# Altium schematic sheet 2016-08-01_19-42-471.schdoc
size 295 x 121 mm; SheetNumber: 1; SheetTotal: 1
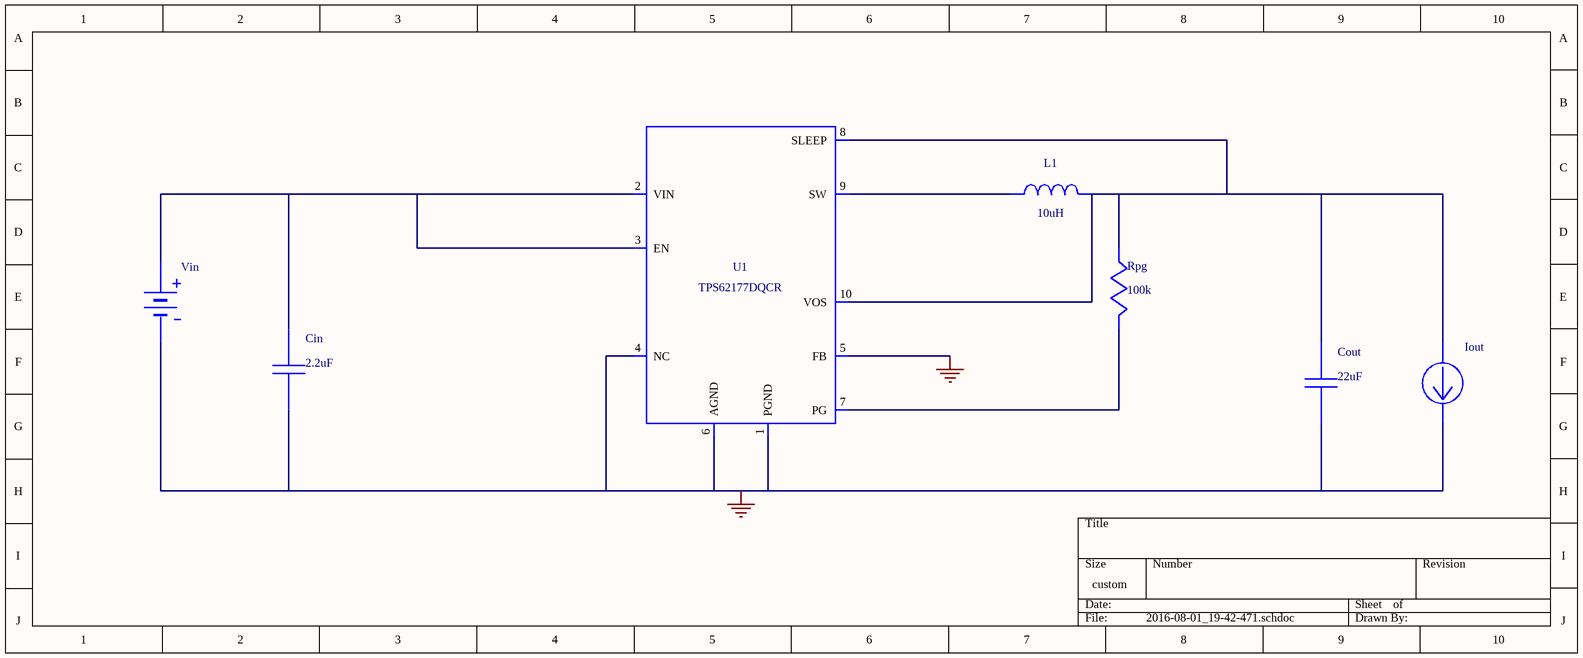
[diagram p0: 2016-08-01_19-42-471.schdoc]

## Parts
Cin  value 2.2uF  (hidden comment: GRM31CR71H225KA88L)
Cout  value 22uF  (hidden comment: GRM21BR60J226ME39L)
Iout  WB_CURRENT_LOAD  (value not drawn)
L1  value 10uH  (hidden comment: 'LPS4018-103MRB')
Rpg  value 100k  (hidden comment: CRCW0402100KFKED)
U1  TPS62175DQCR  (value not drawn)
Vin  WB_BATTERY  (value not drawn)

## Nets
0: Cin.2 Cout.2 Iout.2(-) U1.1(PGND) U1.4(NC) U1.5(FB) U1.6(AGND) U1.11(DAP) Vin.2(-)
NetCin_1: Cin.1 U1.2(VIN) U1.3(EN) Vin.1(+)
NetCout_1: Cout.1 Iout.1(+) L1.2 Rpg.2 U1.8(SLEEP) U1.10(VOS)
NetL1_1: L1.1 U1.9(SW)
NetRpg_1: Rpg.1 U1.7(PG)

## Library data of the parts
Cin = GRM31CR71H225KA88L: GRM31CR71H225KA8; Manufacturer Name: MuRata
Cout = GRM21BR60J226ME39L: GRM21BR60J226ME3; Manufacturer Name: MuRata
L1 = 'LPS4018-103MRB': LPS4018-103MRB; Manufacturer Name: Coilcraft
Rpg = CRCW0402100KFKED: Manufacturer Name: Vishay-Dale
U1 = TPS62175DQCR: TPS62177DQCR; Manufacturer Name: Texas Instruments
